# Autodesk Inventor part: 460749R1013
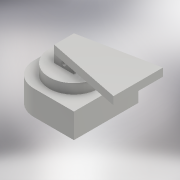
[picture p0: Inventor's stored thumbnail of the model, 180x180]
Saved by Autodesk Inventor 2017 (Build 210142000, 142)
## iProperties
Created: 2016-07
Part Number: 460749R1013
Material: Aluminum 6061
Document SubType Name: Modeling
Designer: Polytech
Mass: 1260.26 g
Surface Area: 611.154 cm^2
Volume: 466.762 cm^3
Density: 2.7 g/cm^3
Appearance: Aluminum - Flat
Author: Polytech
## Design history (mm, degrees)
sketch "Sketch1"
  geometry: C1 r 23 at (0, 0); 1 further point
  constraints: 1 centre point, 1 coincident
  dimensions: "d0" = 46 diameter of C1
extrude "Extrusion1" new body sketch "Sketch1" distance "d1" = 18; taper "d2" = 0 deg
sketch "Sketch2"
  geometry: L1 (-11.75, 48.75)-(48.75, 48.75); L2 (48.75, 48.75)-(48.75, -48.75); L3 (48.75, -48.75)-(-11.75, -48.75); L4 (-48.75, -11.75)-(-48.75, 11.75); L5 (-48.75, 48.75)-(48.75, -48.75); L6 (48.75, 48.75)-(-48.75, -48.75); A1 r 37 centre (-11.75, 11.75) between (-11.75, 48.75) and (-48.75, 11.75); A2 r 37 centre (-11.75, -11.75) between (-48.75, -11.75) and (-11.75, -48.75); 1 further point
  constraints: 12 end point, 4 point on circle, 4 point on line, 4 tangent, 2 centre point, 2 midpoint, 2 parallel, 1 equal radius, 1 horizontal, 1 perpendicular
  dimensions: "d3" = 97.5 distance of L2.end L6.end; "d4" = 97.5 distance of L1.end L2.end; "d5" = 37 radius of A1
extrude "Extrusion2" join sketch "Sketch2" distance "d6" = 37.5; taper "d7" = 0 deg
sketch "Sketch3"
  geometry: C1 r 37.5 at (0, 0); 1 further point
  constraints: 1 centre point, 1 coincident
  dimensions: "d8" = 75 diameter of C1
extrude "Extrusion3" join sketch "Sketch3" distance "d9" = 15; taper "d10" = 0 deg
sketch "Sketch4"
  geometry: L1 (15, 15)-(-15, 15); L2 (-15, 15)-(-15, -15); L3 (-15, -15)-(15, -15); L4 (15, -15)-(15, 15); L5 (15, 15)-(-15, -15); L6 (-15, 15)-(15, -15); 1 further point
  constraints: 12 end point, 2 midpoint, 2 parallel, 1 horizontal, 1 perpendicular
  dimensions: "d11" = 30 distance of L3.end L2.end; "d12" = 30 distance of L2.end L1.end
extrude "Extrusion4" join sketch "Sketch4" distance "d13" = 12; taper "d14" = 0 deg
sketch "Sketch5"
  geometry: L1 (-15, 6)-(15, 6); L2 (15, 6)-(15, -6); L3 (15, -6)-(-15, -6); L4 (-15, -6)-(-15, 6); L5 (-15, 6)-(15, -6); L6 (15, 6)-(-15, -6); 1 further point
  constraints: 12 end point, 2 midpoint, 2 parallel, 1 horizontal, 1 perpendicular
  dimensions: "d15" = 30 distance of L2.end L3.end; "d16" = 12 distance of L1.end L2.end
extrude "Extrusion5" cut sketch "Sketch5" distance "d17" = 12; taper "d18" = 0 deg
sketch "Sketch6"
  geometry: L1 (52.5, 0)-(-22.5, 0) reference; C1 r 3 at (15, 6); 1 further point
  constraints: 1 centre point, 1 vertical alignment
  dimensions: "d19" = 3 radius of C1; "d20" = 6 distance from line of L1 C1.centre
extrude "Extrusion6" cut sketch "Sketch6" stored distance "d21" = 12; taper "d22" = 0 deg
sketch "Sketch7"
  geometry: L1 (-15, 15)-(-15, -15); L2 (-15, -15)-(97.5, -37.5); L3 (97.5, -37.5)-(97.5, 37.5); L4 (97.5, 37.5)-(-15, 15); 4 further points
  constraints: 8 end point, 2 coincident, 1 horizontal alignment, 1 midpoint, 1 parallel, 1 vertical
  dimensions: "d23" = 75 distance of L2.end L3.end; "d24" = 97.5 horizontal distance of L2.end point (0, 0)
extrude "Extrusion7" join sketch "Sketch7" distance "d25" = 12; taper "d26" = 0 deg
sketch "Sketch8"
  geometry: C1 r 23 at (0, 0); 1 further point
  constraints: 1 centre point, 1 coincident
  dimensions: "d27" = 46 diameter of C1
extrude "Extrusion8" cut sketch "Sketch8" distance "d28" = 24.5; taper "d29" = 0 deg
body "Solid1"
